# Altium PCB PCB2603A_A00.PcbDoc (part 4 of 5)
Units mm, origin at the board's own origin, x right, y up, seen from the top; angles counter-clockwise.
Board outline 35.56 x 55.88 mm, 8 copper layers (Top Layer, Signal Layer 1, Signal Layer 2, Signal Layer 3, Signal Layer 4, Signal Layer 5, Signal Layer 6, Bottom Layer), stack 1.497 mm thick; 167 components, 113 nets, 4957 pads, 645 vias.
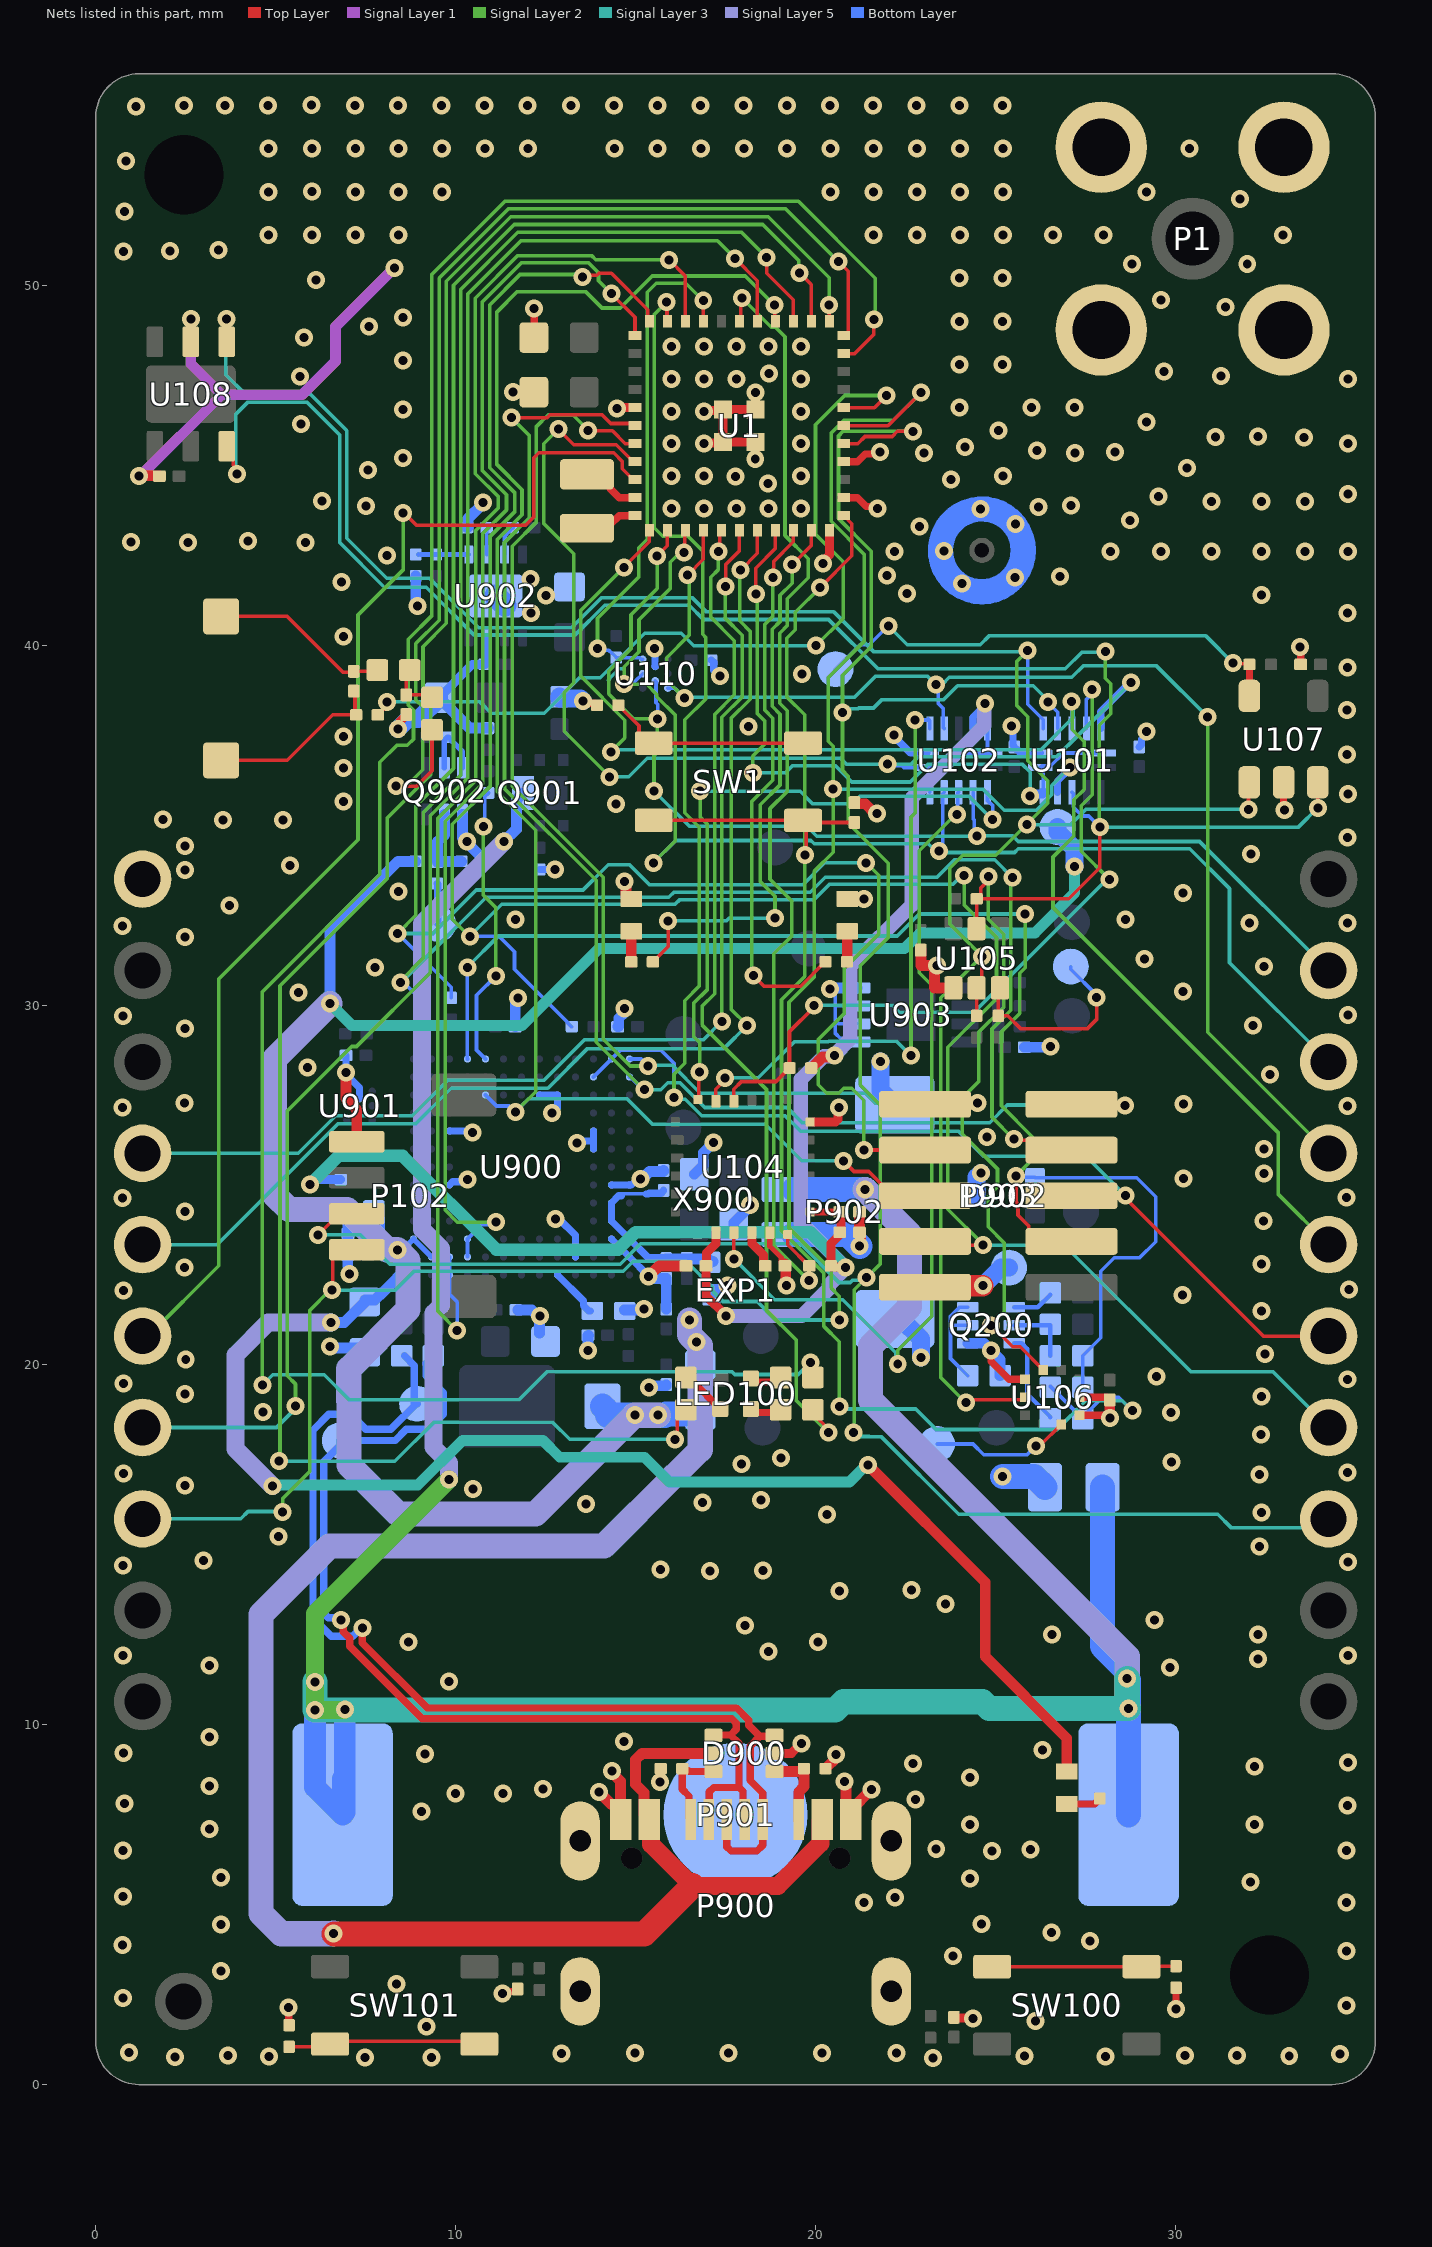
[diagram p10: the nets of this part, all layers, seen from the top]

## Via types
v1: diameter 0.5, hole 0.25, Top Layer to Bottom Layer, tented both sides, 645 vias

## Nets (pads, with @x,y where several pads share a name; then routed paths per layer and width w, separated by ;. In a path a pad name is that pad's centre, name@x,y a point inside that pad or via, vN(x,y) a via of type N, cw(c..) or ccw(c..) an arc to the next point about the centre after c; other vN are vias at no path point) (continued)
DBG_USB_DM: D900.4 P900.A7 P900.B7 R903.1 TPJ19.1 | length 28.1
  Top Layer w0.203: v1(6.82,12.916) 6.877,12.86 6.877,12.584 7.057,12.405 7.057,12.183 9.077,10.163 17.68,10.163 17.8,10.044 17.8,9.875 17.641,9.716 ; P900.B7@17.035,7.36 17.052,7.377 17.052,8.136 17.171,8.255 17.867,8.255 17.876,8.264 ; D900.4@17.165,9.7 17.233,9.7 17.249,9.716 17.641,9.716 ; P900.A7@18.035,7.36 17.987,7.408 17.987,8.153 17.876,8.264 ; 17.641,9.716 17.876,9.481 17.876,8.264
  Bottom Layer w0.203: v1(6.82,12.916) 6.764,12.973 6.464,12.973 6.339,13.098 6.339,17.311 6.78,17.752 TPJ19.1@6.78,17.9 8.32,17.9 8.631,18.211 9.252,18.211 9.659,18.618 9.659,19.222 9.18,19.7 9.18,19.933 9.182,19.934 9.182,20.052 R903.1@9.38,20.25
DBG_USB_DP: D900.3 P900.A6 P900.B6 R904.1 TPJ18.1 | length 30.2
  Top Layer w0.203: v1(7.407,12.694) 7.407,12.27 9.21,10.467 17.806,10.467 18.146,10.127 18.146,9.984 18.455,9.675 ; P900.A6@17.535,7.36 17.535,6.607 17.654,6.488 18.375,6.488 18.533,6.647 18.533,7.358 P900.B6@18.535,7.36 18.531,7.364 18.531,8.101 18.185,8.447 18.185,9.405 18.455,9.675 ; D900.3@18.865,9.7 18.84,9.675 18.455,9.675
  Bottom Layer w0.203: v1(7.407,12.694) 7.373,12.694 7.139,12.46 6.544,12.46 6.036,12.968 6.036,18.186 6.478,18.629 7.082,18.629 7.503,18.208 8.199,18.208 8.911,18.92 TPJ18.1@8.93,18.92 8.851,18.92 8.851,19.979 R904.1@8.58,20.25
DBG_VBUS: C901.1 D901.2 L901.2 R917.2 TPJ12.1 U900.A11 U900.B12 | length 62.2
  Signal Layer 5 w0.7: v1(6.511,30.044) 4.966,28.499 4.966,24.725 5.376,24.315 6.981,24.315 8.096,23.2 8.38,23.2 8.68,22.9 8.68,21.538 7.032,19.891 7.032,19.005 7.035,19.002 7.035,17.22 8.401,15.854 12.219,15.854 14.965,18.6 v1(15.63,18.6)
  Signal Layer 3 w0.305: v1(6.511,30.044) 7.12,29.434 11.849,29.434 13.984,31.569 22.473,31.569 22.913,32.008 26.1,32.008 27.201,33.109 v1(27.201,33.852)
  Bottom Layer w0.152: v1(8.382,23.198) 8.419,23.235 8.565,23.235 U900.A11@8.83,23.5 U900.B12@9.33,23
  Bottom Layer w0.2: C901.1@7.73,24.3 7.935,24.095 7.935,23.645 v1(8.382,23.198)
  Bottom Layer w0.305: v1(6.511,30.044) 6.511,32.102 8.404,33.995 R917.2@8.89,33.995
  Bottom Layer w0.5: TPJ12.1@26.73,34.95 26.73,34.815 27.201,34.343 v1(27.201,33.852)
  Bottom Layer w0.7: D901.2@14.08,18.85 D901.2@14.175,18.755 ; D901.2@14.23,18.6 v1(14.98,18.6) v1(15.63,18.6) 15.82,18.6 15.85,18.631 16.781,18.631 L901.2@16.8,18.65
DBG_VREGO: C902.1 LED900.1 U900.A12 | length 38.8
  Top Layer w0.3: v1(21.462,17.214) 24.716,13.96 24.716,11.892 26.985,9.623 LED900.1@26.985,8.7
  Signal Layer 5 w0.5: v1(4.908,16.633) 3.878,17.663 3.878,20.268 4.786,21.176 v1(6.53,21.176)
  Signal Layer 3 w0.3: v1(4.908,16.633) 4.936,16.66 8.949,16.66 10.189,17.9 12.425,17.9 12.894,17.431 15.252,17.431 15.94,16.743 20.943,16.743 21.414,17.214 v1(21.462,17.214)
  Bottom Layer w0.2: 8.43,22.475 8.43,22.6 U900.A12@8.83,23
  Bottom Layer w0.3: v1@6.531,21.175 6.905,21.175 C902.1@7.48,21.75 ; C902.1@7.48,21.8 7.755,21.8 7.98,22.025 7.987,22.025 8.28,22.318 8.28,22.325 8.43,22.475
DEBUG_PTI_DATA: P903.10 U1.29 U900.N1 | length 34.7
  Top Layer w0.1: v1(13.683,45.973) 13.696,45.96 14.358,45.96 14.718,45.6 U1.29@14.933,45.6
  Top Layer w0.102: P903.10@23.045,27.24 23.081,27.276 v1(24.505,27.276)
  Signal Layer 2 w0.1: v1(13.683,45.973) 13.252,46.404 12.572,46.404 12.246,46.078 12.246,43.422 11.571,42.747 11.571,39.442 11.572,39.441 11.572,36.08 14.105,33.547 14.105,29.052 14.852,28.305 v1(15.35,28.305)
  Signal Layer 3 w0.1: v1(15.35,28.305) 15.37,28.325 16.03,28.325 16.802,27.552 21.389,27.552 21.665,27.276 v1(24.505,27.276)
  Bottom Layer w0.1: U900.N1@14.83,28.5 15.155,28.5 v1(15.35,28.305)
DEBUG_PTI_FRAME: P903.9 U1.28 U900.N2 | length 40.5
  Top Layer w0.1: v1(11.548,46.326) 12.545,46.326 12.623,46.404 14.07,46.404 14.314,46.16 14.925,46.16 U1.28@14.985,46.1 ; P903.9@27.115,27.24 27.134,27.221 28.587,27.221 v1(28.596,27.212)
  Signal Layer 2 w0.1: v1(11.548,46.326) 12.046,45.828 12.046,43.541 11.36,42.855 11.36,36.01 13.905,33.465 13.905,28.969 15.226,27.648 v1(15.255,27.648)
  Signal Layer 3 w0.1: v1(15.255,27.648) 15.705,27.648 15.894,27.837 16.235,27.837 16.92,27.152 19.212,27.152 19.631,26.732 24.842,26.732 25.332,27.222 28.586,27.222 v1(28.596,27.212)
  Bottom Layer w0.1: U900.N2@14.83,28 14.857,28 15.209,27.648 v1(15.255,27.648)
DEBUG_RESET: D902.1 P903.3 R206.1 R209.1 U900.D1 | length 40.4
  Top Layer w0.1: v1(25.573,25.25) 25.573,24.528 25.63,24.471 25.63,24.158 25.93,23.859 25.93,23.748 26.248,23.43 P903.3@27.115,23.43
  Signal Layer 2 w0.1: v1(25.573,25.25) 26.028,25.705 26.028,26.343 25.171,27.2 25.171,29.257 25.681,29.767 25.681,30.886 25.83,31.035 v1(25.83,32.531)
  Signal Layer 3 w0.1: v1(10.326,31.042) 10.326,31.052 11.193,31.919 22.271,31.919 22.883,32.531 v1(25.83,32.531)
  Bottom Layer w0.1: v1(10.326,31.042) 10.328,31.04 10.328,28.502 U900.D1@10.33,28.5 ; v1(25.573,25.25) 25.613,25.21 26.095,25.21 D902.1@26.105,25.2 28.931,25.2 29.455,24.676 29.455,23.425 29.005,22.975 28.305,22.975 27.93,22.6 27.93,20.75 R206.1@27.43,20.25 R209.1@27.43,19.4
DEBUG_SWCLK: P903.8 R920.2 U1.13 | length 59.6
  Top Layer w0.1: v1(19.557,50.35) 19.885,50.022 U1.13@19.885,49 ; v1(21.345,25.97) P903.8@23.045,25.97
  Signal Layer 2 w0.1: v1(8.388,31.989) 8.895,32.495 8.895,35.53 9.941,36.576 9.941,50.004 11.628,51.691 18.532,51.691 19.532,50.691 19.532,50.375 v1(19.557,50.35) ; v1(21.345,25.97) 21.345,27.351 21.005,27.691 20.784,27.691 20.645,27.552 20.314,27.552 20.079,27.786 20.079,29.043 20.805,29.769 20.805,31.025 21.756,31.976 21.756,33.608 v1(21.411,33.952)
  Signal Layer 3 w0.1: v1(8.388,31.989) 9.362,31.989 10.57,33.197 13.541,33.197 14.242,33.898 14.834,33.898 15.394,33.338 19.643,33.338 20.257,33.952 v1(21.411,33.952)
  Bottom Layer w0.1: v1(8.388,31.989) 9.88,30.497 R920.2@9.88,30.2
DEBUG_SWDIO: P903.7 R919.2 U1.14 | length 60.3
  Top Layer w0.1: v1(18.645,50.773) 18.645,50.34 19.385,49.6 U1.14@19.385,49 ; v1(25.515,26.271) 25.542,26.244 26.841,26.244 P903.7@27.115,25.97
  Signal Layer 2 w0.1: v1(8.462,30.629) 8.462,30.663 9.095,31.296 9.095,35.346 10.141,36.392 10.141,49.885 11.73,51.474 17.944,51.474 v1(18.645,50.773) ; v1(25.473,33.545) 25.43,33.502 25.43,29.858 24.905,29.333 24.905,26.881 v1(25.515,26.271)
  Signal Layer 3 w0.1: v1(8.462,30.629) 8.484,30.629 10.852,32.997 15.927,32.997 16.068,33.138 19.855,33.138 20.27,33.552 23.379,33.552 23.864,34.038 24.98,34.038 v1(25.473,33.545)
  Bottom Layer w0.1: v1(8.462,30.629) 8.561,30.629 8.98,30.21 R919.2@8.98,30.2
DEBUG_SWO: P903.6 U1.15 U900.E3 | length 46.5
  Top Layer w0.1: v1(18.863,49.451) 18.874,49.44 18.874,49.011 U1.15@18.885,49 ; v1(20.775,25.671) 21.071,25.375 21.479,25.375 P903.6@21.82,25.034 ; P903.6@21.82,25.033 22.153,24.7 P903.6@23.045,24.7
  Signal Layer 2 w0.1: v1(11.658,27.025) 12.226,27.593 12.226,34.861 11.16,35.927 11.16,42.937 11.846,43.624 11.846,44.322 11.148,45.02 11.148,49.262 11.714,49.828 13.611,49.828 14.068,49.37 14.574,49.37 15.465,50.261 18.053,50.261 v1(18.863,49.451)
  Signal Layer 3 w0.1: v1(11.658,27.025) 11.658,27.028 12.03,27.4 14.756,27.4 15.472,26.685 18.606,26.685 19.62,25.671 v1(20.775,25.671)
  Bottom Layer w0.1: U900.E3@10.83,27.5 11.135,27.195 11.485,27.195 11.655,27.025 v1(11.658,27.025)
EXP_HEADER4: EXP1.4 U1.35 U102.2 U110.D2 | length 32.1
  Top Layer w0.1: v1(15.6,42.48) 15.885,42.765 U1.35@15.885,43.2
  Signal Layer 2 w0.1: v1(15.514,35.945) 15.514,36.936 15.606,37.028 v1@15.606,37.945 ; v1(15.6,42.48) 15.6,41.578 14.873,40.85 14.873,39.899 14.253,39.279 14.253,38.646 14.945,37.955 v1(15.606,37.955)
  Signal Layer 3 w0.1: v1(15.514,35.945) 15.522,35.945 16.493,34.973 19.752,34.973 20.033,34.692 v1(24.492,34.692) 24.503,34.703 25.482,34.703 25.639,34.546 30.675,34.546 EXP1.4@34.261,30.96
  Bottom Layer w0.1: U110.D2@15.547,39.008 15.567,38.987 15.567,38.406 15.618,38.355 15.618,37.967 v1(15.606,37.955) ; U102.2@24.38,35.915 24.38,35.178 24.416,35.142 24.416,34.767 v1(24.492,34.692)
EXP_HEADER6: EXP1.6 U1.36 U102.4 U110.C3 | length 36.1
  Top Layer w0.1: v1(16.34,42.577) 16.363,42.599 16.363,43.178 U1.36@16.385,43.2
  Signal Layer 2 w0.1: v1(14.686,38.917) 14.686,39.403 15.097,39.815 15.097,40.705 15.968,41.577 15.968,42.303 16.242,42.577 v1(16.34,42.577) ; v1@14.692,38.911 15.314,38.911 15.592,38.633 15.592,38.57 16.102,38.06 16.102,34.56 v1(15.495,33.953)
  Signal Layer 3 w0.1: v1(15.495,33.953) 16.114,34.572 19.87,34.572 19.963,34.479 23.132,34.479 23.33,34.281 v1(23.438,34.281) 23.481,34.238 25.531,34.238 25.639,34.346 30.399,34.346 31.508,33.237 31.508,31.173 EXP1.6@34.261,28.42
  Bottom Layer w0.1: v1(14.686,38.917) 14.762,38.994 14.982,38.994 U110.C3@15.197,39.208 ; v1@23.536,34.488 23.536,35.871 U102.4@23.58,35.915
EXP_HEADER7: EXP1.7 U1.39 | length 31.9
  Top Layer w0.1: v1(17.494,41.626) 17.511,41.643 17.511,42.243 17.885,42.617 U1.39@17.885,43.2
  Signal Layer 2 w0.1: v1(17.398,29.546) 17.398,37.994 17.963,38.558 17.963,40.279 17.488,40.755 17.488,41.62 v1(17.494,41.626)
  Signal Layer 3 w0.1: EXP1.7@1.3,25.88 5.625,25.88 6.666,26.921 8.796,26.921 9.787,27.912 12.456,27.912 13.582,29.037 16.889,29.037 v1(17.398,29.546)
EXP_HEADER8: EXP1.8 U1.37 U102.9 U110.E1 | length 36.4
  Top Layer w0.1: v1(16.447,41.948) 16.885,42.386 U1.37@16.885,43.2
  Signal Layer 2 w0.1: v1(16.361,38.53) 16.359,38.53 15.867,39.022 15.867,39.654 16.488,40.275 16.488,41.907 v1(16.447,41.948) ; v1(30.898,38.002) 30.898,29.243 EXP1.8@34.261,25.88
  Signal Layer 3 w0.1: v1(16.361,38.53) 16.389,38.558 21.089,38.558 21.672,39.141 23.111,39.141 23.35,38.902 v1(23.354,38.902) ; v1@23.354,38.907 23.516,38.907 23.714,39.106 27.125,39.106 27.443,39.424 29.477,39.424 v1(30.898,38.002)
  Bottom Layer w0.1: U110.E1@15.897,38.808 16.084,38.808 v1(16.361,38.53) ; v1(23.354,38.902) 23.416,38.84 23.416,38.38 23.552,38.243 23.552,37.713 U102.9@23.58,37.685
EXP_HEADER9: EXP1.9 U1.40 | length 33.8
  Top Layer w0.1: v1(17.92,42.087) 18.385,42.552 U1.40@18.385,43.2
  Signal Layer 2 w0.1: v1(17.92,42.087) 17.894,42.061 17.894,40.675 18.186,40.383 18.186,38.499 17.654,37.967 17.654,29.886 v1(18.103,29.437)
  Signal Layer 3 w0.1: EXP1.9@1.3,23.34 3.368,23.34 6.731,26.702 8.891,26.702 9.88,27.691 12.565,27.691 13.664,28.79 17.456,28.79 v1(18.103,29.437)
EXP_HEADER10: EXP1.10 U1.34 U101.10 | length 40.9
  Top Layer w0.1: v1(14.674,42.163) 15.385,42.874 U1.34@15.385,43.2
  Signal Layer 2 w0.1: v1(14.312,37.035) 14.699,37.422 14.699,37.918 13.482,39.134 13.482,40.971 v1@14.673,42.161 ; v1(27.114,38.433) 27.137,38.409 27.137,37.652 27.47,37.319 27.47,35.992 27.18,35.702 27.18,34.694 26.601,34.115 26.601,32.71 32.866,26.446 32.866,24.735 EXP1.10@34.261,23.34
  Signal Layer 3 w0.1: v1(14.312,37.035) 14.373,37.096 26.268,37.096 27.168,37.997 27.168,38.378 v1(27.114,38.433)
  Bottom Layer w0.1: v1(27.114,38.433) 27.122,38.424 27.122,37.693 U101.10@27.13,37.685
EXP_HEADER11: EXP1.11 U1.31 | length 34.8
  Top Layer w0.1: v1(8.541,43.67) 8.578,43.67 8.914,43.334 11.943,43.334 12.17,43.561 12.17,45.202 12.314,45.345 14.391,45.345 14.63,45.106 14.63,44.905 14.935,44.6 U1.31@14.985,44.6
  Signal Layer 2 w0.1: EXP1.11@1.3,20.8 1.466,20.8 3.417,22.751 3.417,30.725 7.287,34.595 7.287,40.84 8.55,42.103 8.55,43.661 v1(8.541,43.67)
EXP_HEADER12: EXP1.12 P903.5 U1.21 U900.L2 U900.M1 | length 50.6
  Top Layer w0.1: v1(15.866,49.533) 15.875,49.523 15.875,49.01 U1.21@15.885,49 ; P903.5@27.115,24.7 27.117,24.702 v1(28.616,24.702) ; v1@28.579,24.665 32.444,20.8 EXP1.12@34.261,20.8
  Signal Layer 2 w0.1: v1(15.866,49.533) 15.523,49.19 15.523,43.262 15.76,43.025 16.458,43.025 16.865,42.618 16.865,40.3 16.947,40.218 16.947,38.502 16.369,37.924 16.369,35.342 16.774,34.937 16.774,30.528 16.369,30.122 16.369,28.38 16.069,28.08 v1(16.069,27.437)
  Signal Layer 3 w0.1: v1(16.069,27.437) 16.122,27.384 16.382,27.384 16.842,26.924 19.156,26.924 19.587,26.493 23.976,26.493 24.669,25.801 27.517,25.801 v1(28.616,24.702)
  Bottom Layer w0.1: U900.L2@13.83,28 U900.M1@14.33,28.5 14.58,28.75 15.701,28.75 16.069,28.382 v1(16.069,27.437)
EXP_HEADER13: EXP1.13 U1.16 | length 47.9
  Top Layer w0.1: v1(17.764,50.75) 18.385,50.129 U1.16@18.385,49
  Signal Layer 2 w0.1: v1(5.551,18.858) 5.551,19.466 5.32,19.698 5.32,27.055 7.113,28.849 7.248,28.849 9.296,30.897 9.296,35.264 10.341,36.309 10.341,49.762 11.818,51.238 17.276,51.238 v1(17.764,50.75)
  Signal Layer 3 w0.1: EXP1.13@1.3,18.26 5.023,18.26 5.551,18.788 v1(5.551,18.858)
EXP_HEADER14: EXP1.14 P903.4 R921.2 U1.22 | length 67.9
  Top Layer w0.1: v1(13.527,50.228) 13.584,50.284 13.927,50.284 13.977,50.334 14.33,50.334 15.339,49.325 15.339,49.046 U1.22@15.385,49
  Top Layer w0.102: P903.4@23.045,23.43 23.15,23.325 v1(24.655,23.325)
  Signal Layer 2 w0.1: v1(24.133,33.598) 24.133,32.779 25.03,31.882 25.03,30.174 23.68,28.824 23.68,24.325 24.655,23.35 v1(24.655,23.325)
  Signal Layer 2 w0.102: v1(10.394,31.911) 10.379,31.911 9.909,32.381 9.909,35.022 10.959,36.071 10.959,43.021 11.639,43.701 11.639,44.242 10.947,44.934 10.947,49.457 11.79,50.301 13.454,50.301 v1(13.527,50.228)
  Signal Layer 3 w0.1: v1(10.394,31.911) 11.28,32.797 16.097,32.797 16.22,32.921 19.955,32.921 20.387,33.352 23.813,33.352 24.059,33.598 v1(24.133,33.598) ; v1(24.655,23.325) 26.917,23.325 30.437,19.805 32.716,19.805 EXP1.14@34.261,18.26
  Bottom Layer w0.1: 11.206,31.911 11.637,31.479 11.637,30.993 13.11,29.52 13.11,29.51 13.22,29.4 R921.2@13.23,29.4
  Bottom Layer w0.102: v1(10.394,31.911) 11.206,31.911
EXP_HEADER15: EXP1.15 P102.4 U1.6 U101.4 | length 68.5
  Top Layer w0.1: v1(6.569,22.076) 6.587,22.094 6.587,22.952 6.835,23.2 P102.4@7.255,23.2 ; U1.6@20.785,46.1 22.014,46.1 v1(22.931,47.017)
  Signal Layer 2 w0.1: EXP1.15@1.3,15.72 EXP1.15@1.442,15.578 ; v1(5.192,15.906) 5.192,16.288 5.951,17.047 5.951,21.522 6.505,22.076 v1(6.569,22.076) ; v1(20.665,21.248) 20.665,21.909 20.436,22.138 20.436,22.634 19.266,23.804 19.266,30.074 19.969,30.777 19.969,33.722 20.491,34.245 v1(20.491,35.997) 20.491,37.194 20.352,37.332 20.352,39.104 21.352,40.103 21.352,42.53 20.441,43.441 20.441,45.899 20.791,46.248 22.162,46.248 v1(22.931,47.017)
  Signal Layer 3 w0.1: EXP1.15@1.3,15.72 4.027,15.72 4.233,15.926 5.172,15.926 v1(5.192,15.906) ; v1(6.569,22.076) 8.318,22.076 8.841,22.6 14.658,22.6 14.935,22.877 16.408,22.877 17.151,22.134 17.151,22.041 17.429,21.762 18.379,21.762 18.893,21.248 v1(20.665,21.248) ; v1(20.491,35.997) 24.657,35.997 25.243,35.41 26.133,35.41 26.563,35.84 26.563,36.099 v1(27.07,36.605)
  Bottom Layer w0.1: U101.4@26.73,35.915 26.78,35.965 U101.4@26.78,36.205 ; v1@27.07,36.595 v1(27.07,36.605)
  Bottom Layer w0.2: U101.4@26.73,35.915 26.73,36.226 27.07,36.566 v1@27.07,36.595
EXP_HEADER16: EXP1.16 P102.3 U1.5 U101.9 | length 73.1
  Top Layer w0.1: v1(6.175,23.615) 6.185,23.615 6.755,24.185 6.755,24.2 P102.3@7.255,24.2 ; U1.5@20.785,45.6 21.176,45.6 21.376,45.8 22.13,45.8 22.273,45.943 v1(22.714,45.943)
  Signal Layer 2 w0.1: v1(21.058,18.114) 21.08,18.136 21.08,22.085 v1(21.42,22.425) 21.795,22.8 21.795,27.225 21.241,27.78 21.241,31.091 22.027,31.877 22.027,33.941 20.912,35.056 20.912,36.362 20.752,36.521 20.752,38.255 20.752,39.163 21.553,39.964 21.553,42.611 20.641,43.523 20.641,45.816 20.768,45.943 v1(22.714,45.943)
  Signal Layer 3 w0.1: v1(6.175,23.615) 7.349,23.615 8.166,22.798 8.756,22.798 8.759,22.8 14.575,22.8 15.14,23.365 19.58,23.365 20.655,22.29 20.97,22.29 21.029,22.348 21.343,22.348 v1(21.42,22.425) ; v1(20.752,38.13) 20.86,38.238 21.185,38.238 21.202,38.255 21.616,38.255 21.85,38.489 23.566,38.489 23.95,38.873 26.057,38.873 26.46,38.47 v1(26.46,38.421) ; v1(21.058,18.114) 21.161,18.01 21.495,18.01 21.508,17.998 21.837,17.998 23.984,15.85 31.177,15.85 31.549,15.478 34.019,15.478 EXP1.16@34.261,15.72
  Bottom Layer w0.1: v1(26.46,38.421) 26.46,38.41 26.73,38.139 U101.9@26.73,37.685
FLASH_SPI_CS: R100.1 U1.19 U110.A3 | length 14.3
  Top Layer w0.1: v1(16.882,49.575) 16.883,49.574 16.883,49.002 U1.19@16.885,49
  Signal Layer 2 w0.1: v1(13.944,39.904) 13.944,40.751 15.086,41.893 15.086,42.706 15.323,42.943 15.323,49.811 15.573,50.061 16.396,50.061 v1(16.882,49.575)
  Bottom Layer w0.1: v1(13.944,39.904) 13.993,39.855 14.26,39.855 14.34,39.775 14.35,39.775 14.46,39.665 R100.1@14.46,39.655 15.12,39.655 15.167,39.608 U110.A3@15.197,39.608
GND: C22.2 C23.2 C100.2 C101.2 C104.2 C105.2 C106.2 C107.2 C110.2 C111.2 C112.2 C113.2 C114.2 C115.2 C142.2 C145.2 C199.2 C900.2 C901.2 C902.2 C903.2 C904.2 C905.2 C907.2 C908.2 C909.2 C910.2 C911.2 C914.2 C915.2 C916.2 C917.2 C918.2 C919.2 C920.2 C921.2 C923.2 C924.2 C925.2 C926.2 D900.2 D902.3 EXP1.1 LED0.2 LED1.2 P1.2 P1.3 P1.4 P1.5 P102.1 P900.A1_B12 P900.B1_A12 P900.S1 P900.S2 P900.S3 P900.S4 P901.2 P902.1 P902.3 P902.4 P903.2 Q200.1 Q902.1 R6.1 R141.2 R144.2 R208.1 R620.1 R621.1 R909.1 R915.1 R916.1 R933.2 TP1.2 TPJ13.1 U1.2 U1.4 U1.27 U1.44 U1.45 U1.46 U1.47 U1.48 U101.7 U102.7 U104.11 U104.18 U105.1 U106.3 U106.8 U106.9 U107.2 U108.2 U110.B2 U900.C5 U900.C8 U900.H3 U900.J3 U900.K11 U900.K12 U900.L5 U900.L6 U900.M8 U900.M11 U900.N8 U900.N12 U901.B2 U902.3 U902.9 U903.1 U903.2 U903.3 U903.4 X900.2 X900.4 | length 99.1
  Top Layer w0.15: U104.11@18.73,23.675 18.73,23.301 19.05,22.981 19.05,22.835 19.085,22.8 C106.2@19.155,22.8
  Top Layer w0.2: v1(5.357,2.142) 5.365,2.135 5.365,1.656 R144.2@5.372,1.648 ; v1(11.307,2.528) 11.364,2.585 11.66,2.585 11.72,2.645 C145.2@11.72,2.655 ; v1(11.595,47.038) 12.167,47.038 C111.2@12.173,47.032 ; v1(12.184,49.363) 12.184,48.372 C110.2@12.195,48.361 ; v1(13.54,38.45) 13.622,38.45 13.684,38.388 13.867,38.388 R6.1@13.927,38.328 ; U1.2@20.71,44.1 21.17,44.1 21.413,43.857 21.671,43.857 v1(21.729,43.799) ; U1.4@20.79,45.106 20.854,45.106 20.86,45.1 21.17,45.1 21.385,45.316 21.739,45.316 v1(21.796,45.373) ; v1(24.88,20.4) 24.88,20.1 25.38,19.6 U106.3@25.823,19.6 ; U106.8@27.337,18.6 28.105,18.6 v1(28.18,18.525) ; U106.9@27.337,19.1 28.105,19.1 C112.2@28.18,19.025 ; v1(30.022,2.105) R141.2@30.022,2.69 ; U107.2@33.01,36.19 33.01,35.455 v1(33.039,35.427) ; v1(33.461,39.955) 33.485,39.931 C113.2@33.485,39.465
  Top Layer w0.25: v1(8.405,37.677) 8.452,37.725 8.452,37.877 8.625,38.05 C199.2@8.625,38.07 ; v1(14.484,46.583) 14.501,46.6 U1.27@14.985,46.6 ; v1(15.679,8.403) 15.69,8.414 15.69,8.77 R621.1@15.7,8.781 ; v1(16.9,45.6) 16.925,45.625 17.41,45.625 U1.48@17.435,45.65 ; v1(16.9,46.5) 16.925,46.525 17.41,46.525 U1.47@17.435,46.55 ; v1(18.327,45.177) 18.331,45.181 18.331,45.646 U1.45@18.335,45.65 U1.48@17.435,45.65 ; v1(18.339,47.026) 18.337,47.024 18.337,46.552 U1.46@18.335,46.55 U1.47@17.435,46.55 ; D900.2@18.865,9.2 19.329,9.2 19.6,9.471 v1(19.611,9.471) ; U104.18@19.955,26.75 20.555,26.75 20.63,26.825 20.63,27.125 v1(20.655,27.15) ; v1(20.209,42.27) 20.209,42.325 20.385,42.501 U1.44@20.385,43.2 ; C142.2@23.85,1.869 23.864,1.855 24.361,1.855 v1(24.375,1.84) ; U1.48@17.435,45.65 U1.47@17.435,46.55
  Top Layer w0.3: v1@1.355,44.726 1.301,44.726 1.316,44.71 1.755,44.71 C114.2@1.765,44.7 ; U108.2@2.64,48.43 v1(2.64,49.065) ; v1(6.955,28.125) 6.955,27.4 7.255,27.1 P102.1@7.255,26.2 ; v1@13.999,8.115 14.334,7.78 14.435,7.78 P900.A1_B12@14.585,7.63 ; v1(14.348,8.717) 14.348,8.663 14.585,8.426 P900.A1_B12@14.585,7.36 ; v1(14.699,33.434) 14.737,33.395 14.737,33.025 14.812,32.95 LED1.2@14.885,32.95 ; v1(15.356,22.451) 15.655,22.75 C115.2@16.405,22.75 ; C106.2@19.155,22.8 C106.2@19.155,22.75 19.163,22.75 19.173,22.74 19.173,22.226 v1(19.191,22.208) ; R620.1@20.279,8.789 20.289,8.789 20.575,9.075 v1(20.575,9.167) ; v1(20.811,8.424) 20.849,8.386 20.849,7.661 P900.B1_A12@20.88,7.63 ; P900.B1_A12@20.985,7.36 20.985,7.63 21.55,8.195 v1(21.554,8.195) ; C100.2@21.083,35.623 21.083,35.603 21.093,35.593 21.382,35.593 21.652,35.324 v1(21.706,35.324) ; C104.2@21.225,23.682 C105.2@21.225,24.25 ; v1(21.229,23.298) 21.259,23.327 C104.2@21.259,23.672 ; v1(21.355,32.952) v1(21.355,32.952) LED0.2@20.886,32.951 ; C107.2@22.93,31.525 22.93,31.1 v1(23.38,31.1) 23.305,31.025 23.305,30.475 U105.1@23.83,30.475 ; v1(26.535,28.842) v1@26.535,28.857 ; v1(28.18,18.525) C112.2@28.18,19.025 ; LED0.2@20.886,32.951 LED0.2@20.885,32.95 LED0.2@20.886,32.951
  Top Layer w0.6: P903.2@23.045,22.16 23.085,22.2 v1(24.655,22.2)
  Signal Layer 1 w0.2: v1(30.022,2.105) v1@30.022,2.142
  Signal Layer 1 w0.3: v1(1.2,44.7) 1.235,44.7 3.498,46.963 ; v1(2.64,49.065) 2.64,47.821 3.498,46.963 ; v1(8.296,50.486) 6.661,48.85 6.661,47.889 5.734,46.963 3.498,46.963
  Signal Layer 3 w0.1: 14.25,39.028 14.286,39.064 14.286,39.083 14.548,39.345 14.637,39.345
  Bottom Layer w0.1: v1(20.405,30.45) 20.555,30.3 20.555,30 ; U903.1@21.155,28.975 21.055,29.075 20.689,29.075 20.555,29.209 20.555,29.575 ; U903.2@21.155,29.475 20.655,29.475 20.555,29.575 ; U903.3@21.155,29.975 20.58,29.975 20.555,30 ; 20.555,29.575 20.555,30
  Bottom Layer w0.2: U900.C8@9.83,25 9.918,25.088 10.268,25.088 v1(10.326,25.146) ; U900.C5@9.83,26.5 10.438,26.5 v1(10.475,26.463) ; U900.H3@12.33,27.5 U900.J3@12.83,27.5 12.83,27.125 v1@12.705,27 ; R915.1@12.34,33.77 12.759,33.77 v1(12.76,33.771) ; v1@12.73,24.05 v1(12.78,24.05) 12.88,24.05 13.33,23.6 U900.K11@13.33,23.5 U900.K12@13.33,23 ; v1@13.375,26.22 13.8,26.22 13.83,26.25 ; U900.L6@13.83,26 13.83,26.25 ; U900.L5@13.83,26.5 13.83,26.25 ; U900.M11@14.33,23.5 U900.N12@14.83,23 15.354,22.476 v1(15.356,22.451) ; U900.M8@14.33,25 14.886,25 15.056,25.17 v1(15.137,25.17) ; v1(15.534,39.914) 15.545,39.903 15.545,39.41 U110.B2@15.547,39.408 ; C101.2@17.094,39.588 17.114,39.588 17.174,39.528 17.174,39.3 17.332,39.142 v1(17.347,39.142) ; v1(22.189,37.499) 22.189,37.459 22.648,37 U102.7@23.095,37 ; v1(25.447,37.753) 25.489,37.712 25.489,37.216 C23.2@25.53,37.175 25.53,37.155 25.59,37.095 25.612,37.095 25.707,37 U101.7@26.245,37 ; C22.2@29,37.175 29.06,37.235 29.06,37.384 29.195,37.519 v1(29.195,37.6)
  Bottom Layer w0.203: C914.2@6.955,28.6 v1(6.955,28.125) 6.955,28.075 7.33,27.7 U901.B2@7.33,27.4
  Bottom Layer w0.25: C915.2@9.54,38.545 10.465,39.47 C916.2@10.815,39.47 10.865,39.52 U902.3@10.865,40.22 ; v1@19.611,9.46 v1(19.611,9.471)
  Bottom Layer w0.3: C901.2@6.83,24.325 7.005,24.15 C910.2@7.005,23.65 C926.2@7.005,23.05 v1@7.005,22.75 ; R909.1@8.89,41.92 8.89,41.26 8.903,41.248 8.903,41.127 v1(8.941,41.089) ; C908.2@11.655,29.4 11.655,30.11 11.733,30.188 v1(11.733,30.194) ; C911.2@11.729,21.525 12.115,21.525 12.287,21.353 v1(12.341,21.353) 12.341,21.271 12.33,21.261 C907.2@12.33,20.88 ; v1(13.68,20.406) 13.678,20.408 13.678,20.815 C923.2@13.701,20.815 ; C925.2@14.505,29.4 14.525,29.4 14.535,29.41 14.535,29.631 14.659,29.755 14.659,29.87 v1(14.697,29.908) ; C900.2@14.684,21.534 14.691,21.527 15.206,21.527 v1(15.234,21.555) ; v1(15.137,25.17) 15.191,25.17 15.391,25.37 15.77,25.37 15.78,25.38 C905.2@15.78,25.4 ; v1(15.356,22.451) 15.407,22.4 C904.2@15.855,22.4 C924.2@15.855,21.55 ; v1(15.371,19.37) 15.425,19.37 15.475,19.42 15.845,19.42 15.855,19.43 C909.2@15.855,19.45 ; X900.2@16.63,25.3 16.88,25.55 16.88,25.894 17.139,26.154 17.139,26.158 v1(17.16,26.179) ; C903.2@17.105,21.95 17.205,22.05 17.205,22.1 17.39,22.1 17.496,22.206 v1(17.551,22.206) ; X900.4@17.73,23.9 17.73,23.95 18.186,24.406 v1(18.186,24.436) ; v1(20.405,30.45) 20.43,30.475 U903.4@21.155,30.475 ; Q200.1@24.23,20.6 24.68,20.6 v1(24.88,20.4) 25.13,20.15 R208.1@25.13,19.7 ; C919.2@25.805,28.825 26.514,28.825 26.531,28.842 v1(26.535,28.842)
  Bottom Layer w0.305: v1(6.514,20.505) 6.552,20.467 7.363,20.467 C902.2@7.48,20.35 ; C915.2@9.54,38.545 10.39,37.695 R933.2@10.915,37.695 ; v1@10.19,34.636 10.747,34.078 10.747,34.003 10.755,33.995 R916.1@10.765,33.995 ; Q902.1@10.19,35.295 10.192,35.293 10.192,34.715 10.31,34.598 v1(10.31,34.545) ; C918.2@10.315,43.27 10.335,43.27 10.343,43.278 10.343,43.517 10.758,43.932 v1(10.758,43.96)
  Bottom Layer w0.5: v1(8.405,37.677) 8.683,37.955 8.975,37.955 9.54,38.52 C915.2@9.54,38.545 ; C920.2@12.89,38.57 12.89,38.52 13.47,38.52 v1(13.54,38.45) ; v1(21.805,28.425) 21.805,27.625 P902.3@22.205,27.225 ; P902.4@22.205,21.275 22.382,21.275 22.932,20.725 v1(22.932,20.202) ; D902.3@24.455,24.7 24.48,24.725 24.48,25.216 v1(24.602,25.337) ; v1(24.655,22.2) 25.155,22.7 TPJ13.1@25.38,22.7
  Bottom Layer w0.635: U902.9@11.115,41.37 U902.9@11.374,41.111
  Bottom Layer w0.7: P902.1@19.405,23.625 20.902,23.625 v1(21.229,23.298) ; v1(25.205,16.9) 26.08,16.9 C921.2@26.38,16.6
  other v1: 23.273,0.738 2.207,0.764 7.485,0.75 9.332,0.75 4.817,0.776 25.815,0.791 28.065,0.778 33.167,0.794 3.678,0.801 30.269,0.812 31.717,0.801 34.579,0.846 12.943,0.864 0.918,0.886 14.98,0.875 17.58,0.875 20.18,0.875 22.257,0.875 9.194,1.614 26.11,1.763 34.753,2.193 0.758,2.403 8.351,2.794 3.48,3.152 23.817,3.575 34.753,3.708 0.749,3.878 27.626,3.99 26.566,4.231 3.48,4.452 24.609,4.466 21.355,5.059 34.753,5.056 22.205,5.2 0.758,5.231 32.097,5.632 24.294,5.732 3.48,5.752 0.763,6.502 24.904,6.495 34.753,6.5 25.972,6.533 23.357,6.55 3.155,7.1 24.294,7.222 32.197,7.232 9.046,7.593 34.792,7.75 0.793,7.813 22.777,7.924 11.315,8.082 9.993,8.093 13.983,8.131 12.435,8.217 3.155,8.3 24.294,8.532 32.197,8.832 22.705,8.925 34.798,8.95 9.151,9.18 0.767,9.21 26.309,9.295 14.684,9.535 3.155,9.652 9.809,11.207 29.856,11.586 3.155,11.652 32.297,11.832 0.758,11.924 34.798,11.928 18.697,12.032 8.697,12.296 20.076,12.293 26.58,12.501 32.3,12.5 18.036,12.757 29.428,12.907 23.608,13.352 20.673,13.713 22.665,13.738 17.076,14.268 18.547,14.285 15.697,14.31 0.759,14.419 34.805,14.526 2.988,14.562 32.335,14.953 5.078,15.229 20.322,15.841 32.4,15.9 13.619,16.136 16.855,16.171 18.487,16.243 10.484,16.554 2.485,16.645 0.767,16.975 32.347,16.951 34.779,17.002 17.948,17.243 29.892,17.3 19.04,17.413 32.378,18.067 29.875,18.676 4.648,18.696 32.397,19.127 2.485,19.185 0.767,19.487 34.786,19.6 29.477,19.67 2.5,20.144 32.5,20.3 32.4,21.5 30.195,21.935 0.766,22.071 34.824,22.101 7.055,22.525 2.472,22.702 32.4,22.8 32.454,24.004 2.485,24.265 0.74,24.634 34.76,24.654 30.222,25.182 32.466,25.325 32.466,25.995 13.375,26.17 24.765,26.33 12.68,27 0.749,27.155 34.792,27.188 30.222,27.255 2.462,27.28 32.638,28.069 5.888,28.266 2.485,29.345 32.157,29.426 0.758,29.702 34.798,29.728 5.628,30.354 30.213,30.373 7.756,31.04 32.466,31.075 29.146,31.283 2.485,31.885 0.74,32.196 32.061,32.286 34.779,32.281 11.664,32.38 28.62,32.377 3.719,32.766 30.213,33.114 8.416,33.155 2.485,33.755 5.396,33.876 32.1,34.2 2.485,34.425 34.792,34.66 1.874,35.157 3.534,35.139 5.203,35.148 14.463,35.586 6.88,35.657 34.805,35.859 6.88,36.581 34.773,36.968 6.88,37.468 18.143,37.746 34.773,38.193 19.63,39.195 34.786,39.379 6.887,40.246 12.094,40.889 34.786,40.901 12.513,41.376 32.4,41.4 22.55,41.431 24.071,41.72 6.833,41.762 12.079,41.835 25.549,41.885 26.8,41.906 21.988,41.93 8.099,42.492 22.2,42.6 28.2,42.6 29.6,42.6 31,42.6 32.4,42.6 33.6,42.6 34.8,42.6 23.577,42.613 2.564,42.857 5.83,42.857 0.98,42.868 4.224,42.889 22.894,43.303 25.556,43.371 28.743,43.472 24.584,43.779 16,43.8 16.9,43.8 17.8,43.8 18.7,43.8 19.596,43.8 26.192,43.842 7.511,43.874 27.099,43.889 31,44 32.4,44 33.6,44 6.286,44.004 29.538,44.13 34.8,44.2 18.681,44.487 23.766,44.603 17.776,44.683 16,44.7 16.9,44.7 19.596,44.7 25.218,44.703 7.564,44.868 30.332,44.925 8.54,45.204 23.022,45.341 27.215,45.346 28.325,45.373 26.16,45.415 24.155,45.508 16,45.6 19.596,45.6 34.8,45.6 33.571,45.774 31.122,45.79 32.299,45.796 25.092,45.966 5.708,46.147 29.2,46.2 16,46.5 19.596,46.5 8.54,46.555 24,46.6 26,46.6 27.2,46.6 16,47.4 16.9,47.4 17.8,47.4 19.596,47.4 34.8,47.4 5.671,47.461 31.268,47.475 18.707,47.548 29.685,47.608 24,47.8 25.2,47.8 8.54,47.914 16,48.3 16.9,48.3 17.8,48.3 18.7,48.3 19.596,48.3 5.789,48.546 7.598,48.861 24,49 25.2,49 8.54,49.105 31.4,49.4 29.6,49.6 6.116,50.142 24,50.2 25.2,50.2 28.8,50.6 32,50.6 0.772,50.944 2.068,50.952 3.409,50.989 4.8,51.4 6.008,51.403 7.215,51.398 8.415,51.398 21.615,51.398 22.815,51.398 24.015,51.398 25.215,51.398 26.6,51.4 28,51.4 33,51.4 0.794,52.047 31.8,52.4 4.8,52.6 6.008,52.603 7.215,52.598 8.415,52.598 9.615,52.598 20.415,52.598 21.615,52.598 22.815,52.598 24.015,52.598 25.215,52.598 29.2,52.6 0.839,53.462 4.8,53.8 6.008,53.803 7.215,53.798 8.415,53.798 9.615,53.798 10.815,53.798 12.015,53.798 14.415,53.798 15.615,53.798 16.815,53.798 18.015,53.798 19.215,53.798 20.415,53.798 21.615,53.798 22.815,53.798 24.015,53.798 25.215,53.798 30.4,53.8 1.122,54.975 2.448,54.997 3.588,55.005 4.788,55.005 5.996,55.008 7.204,55.003 8.404,55.003 9.604,55.003 10.804,55.003 12.004,55.003 13.204,55.003 14.404,55.003 15.604,55.003 16.804,55.003 18.004,55.003 19.204,55.003 20.404,55.003 21.604,55.003 22.804,55.003 24.004,55.003 25.204,55.003
IMU_ENABLE: U1.30 U101.12 U102.5 U102.6 U102.12 U102.13 | length 35.2
  Top Layer w0.1: v1(12.855,46.004) 13.286,45.573 14.462,45.573 14.935,45.1 U1.30@14.985,45.1
  Top Layer w0.2: v1(28.764,38.96) v1@28.764,38.963
  Signal Layer 2 w0.1: v1(12.855,46.004) 12.446,45.595 12.446,43.38 13.282,42.544 13.282,38.956 13.015,38.688 13.015,37.605 v1(14.28,36.34)
  Signal Layer 3 w0.1: v1(14.28,36.34) 14.81,36.34 15.327,36.858 20.696,36.858 20.857,36.696 v1(22.007,36.696) 22.67,36.696 22.87,36.896 26.7,36.896 27.309,37.505 v1(28.764,38.96)
  Bottom Layer w0.1: v1(22.007,36.696) 22.054,36.649 22.404,36.649 22.454,36.599 ; 22.455,36.6 U102.6@23.095,36.6 ; U102.5@23.18,35.915 23.18,36.515 U102.6@23.095,36.6 ; U102.12@24.78,37.685 24.78,37.085 U102.13@24.865,37 23.78,37 23.38,36.6 U102.6@23.095,36.6
  Bottom Layer w0.2: U101.12@27.93,37.685 27.93,38.154 28.736,38.96 v1(28.764,38.96)
IMU_INT: R103.2 U1.17 U104.12 | length 31.8
  Top Layer w0.1: U1.17@17.885,49 17.919,49.034 17.919,49.619 v1(17.952,49.653) ; U104.12@19.23,23.625 19.23,23.34 19.82,22.75 R103.2@19.83,22.75 19.83,22.347 v1(19.822,22.339)
  Signal Layer 2 w0.1: v1(17.952,49.653) 18.768,48.837 18.888,48.837 19.153,48.572 19.153,43.051 19.797,42.406 19.797,41.874 19.215,41.291 19.215,40.545 19.005,40.336 19.005,38.384 19.215,38.175 19.215,35.936 18.738,35.46 18.738,33.495 19.343,32.89 19.343,31.919 18.845,31.421 18.845,23.316 v1(19.822,22.339)
IMU_SPI_CIPO: U102.3 U104.9 | length 23.6
  Top Layer w0.1: U104.9@17.73,23.675 17.73,22.949 v1(17.734,22.945)
  Signal Layer 2 w0.1: v1(22.287,20.03) 22.287,20.405 23.236,21.354 23.236,30.547 22.883,30.9 22.883,34.292 23.881,35.29 v1(23.936,35.29)
  Signal Layer 3 w0.1: v1(17.734,22.945) 18.871,21.808 20.76,21.808 22.23,20.339 22.23,20.087 v1(22.287,20.03)
  Bottom Layer w0.1: v1(23.936,35.29) 23.958,35.312 23.958,35.893 U102.3@23.98,35.915
IMU_SPI_COPI: U102.1 U104.24 | length 18.3
  Top Layer w0.1: U104.24@16.73,27.375 16.756,27.401 16.756,28.113 v1(16.782,28.139)
  Signal Layer 2 w0.1: v1(16.782,28.139) 16.782,28.959 16.622,29.118 16.622,30.056 16.998,30.432 16.998,35.026 16.798,35.226 v1(16.798,35.942)
  Signal Layer 3 w0.1: v1(16.798,35.942) 19.573,35.942 19.918,35.597 21.037,35.597 21.237,35.797 24.275,35.797 v1(24.922,35.15)
  Bottom Layer w0.1: U102.1@24.78,35.915 24.78,35.675 24.846,35.609 24.864,35.609 24.922,35.55 v1(24.922,35.15)
IMU_SPI_CS: R102.2 U101.11 U104.22 | length 20.8
  Top Layer w0.102: U104.22@17.73,27.325 17.73,27.66 17.945,27.875 18.905,27.875 R102.2@19.28,28.25 19.28,29.263 19.958,29.941 v1(19.958,29.99)
  Signal Layer 2 w0.1: v1(27.688,38.765) 27.691,38.762 27.691,35.841 27.385,35.535 27.385,34.273 v1(28.17,33.488)
  Signal Layer 3 w0.1: v1(19.958,29.99) 22.143,29.99 22.33,29.803 24.407,29.803 28.092,33.488 v1(28.17,33.488)
  Bottom Layer w0.102: U101.11@27.53,37.685 27.53,38.499 27.688,38.657 v1(27.688,38.765)
IMU_SPI_SCLK: U102.8 U104.23 | length 16.6
  Top Layer w0.102: U104.23@17.23,27.325 17.23,27.658 17.48,27.908 v1(17.48,27.977)
  Signal Layer 2 w0.1: v1(22.655,28.593) 22.655,35.222 22.772,35.34 v1(22.772,37.922)
  Signal Layer 3 w0.1: v1(17.48,27.977) 18.414,27.977 19.418,28.982 20.355,28.982 20.368,28.995 22.253,28.995 v1(22.655,28.593)
  Bottom Layer w0.102: v1(22.772,37.922) 23.131,37.922 23.131,37.954 23.18,37.905 U102.8@23.18,37.685
LED0: R29.2 U1.42 | length 15.5
  Top Layer w0.1: v1(18.272,30.824) 18.57,30.526 19.593,30.526 20.267,31.2 R29.2@20.277,31.2 ; v1(18.815,41.878) 18.838,41.902 18.838,42.328 19.385,42.875 U1.42@19.385,43.2
  Signal Layer 2 w0.1: v1(18.272,30.824) 18.272,30.871 18.23,30.913 18.23,35.658 18.815,36.243 18.815,37.973 18.596,38.191 18.596,40.581 18.815,40.799 v1(18.815,41.878)
LED1: R30.2 U1.43 | length 16.1
  Top Layer w0.1: R30.2@15.481,31.2 15.491,31.2 15.601,31.31 15.601,31.32 15.907,31.626 v1(15.907,32.342) ; v1(18.876,32.417) v1@18.905,32.417 ; v1(19.352,42.238) 19.885,42.771 U1.43@19.885,43.2
  Signal Layer 2 w0.1: v1(18.876,32.417) 18.876,33.02 18.465,33.431 18.465,35.562 19.015,36.112 19.015,38.082 18.796,38.3 18.796,40.44 19.015,40.659 19.015,41.384 19.352,41.721 v1(19.352,42.238)
  Signal Layer 3 w0.1: v1(15.907,32.342) 17.528,32.342 17.603,32.417 v1(18.876,32.417)
LESENSE_LC_EXCITE: R198.1 U1.11 | length 32
  Top Layer w0.1: v1(8.35,36.083) 8.915,36.083 9.344,36.512 R198.1@9.344,37.65 ; v1(20.635,50.664) 20.91,50.389 20.91,48.675 20.835,48.6 U1.11@20.785,48.6
  Signal Layer 2 w0.1: v1(8.35,36.083) 8.392,36.125 8.673,36.125 9.084,36.536 9.084,38.286 8.893,38.477 8.893,40.045 9.541,40.693 9.541,50.203 11.463,52.125 19.175,52.125 v1(20.635,50.664)
LESENSE_LC_SENSE: R196.1 U1.7 | length 24
  Top Layer w0.1: R196.1@7.836,38.064 7.846,38.064 8.016,38.234 8.016,38.347 v1(8.093,38.424) ; U1.7@20.785,46.6 21.639,46.6 v1(21.98,46.941)
  Signal Layer 2 w0.1: v1(20.009,39.985) 20.768,40.745 20.768,42.315 20.001,43.083 20.001,46.124 20.817,46.941 v1(21.98,46.941)
  Signal Layer 3 w0.1: v1(8.093,38.424) 10.675,38.424 10.989,38.111 12.459,38.111 13.444,39.095 14.015,39.095 15.255,40.335 16.27,40.335 16.62,39.985 v1(20.009,39.985)
MODULE_#RESET: C100.1 R209.2 R212.2 SW1.1 SW1.2 U1.1 | length 45.3
  Top Layer w0.1: SW1.2@15.505,35.13 SW1.1@19.655,35.13 SW1.1@19.712,35.073 ; v1(19.704,34.172) 19.74,34.208 19.74,34.856 19.796,34.912 19.873,34.912 SW1.1@19.712,35.073 ; v1(20.124,41.6) 21.008,42.484 21.008,43.377 20.91,43.475 20.91,43.525 20.835,43.6 U1.1@20.785,43.6 ; C100.1@21.083,35.073 SW1.1@19.712,35.073
  Signal Layer 2 w0.1: v1(20.124,41.6) 19.441,40.916 19.441,40.426 19.205,40.191 19.205,38.562 19.704,38.063 v1(19.704,34.172) 19.704,30.795 19.057,30.148 19.057,23.729 20.236,22.55 20.236,21.068 20.665,20.639 v1(20.665,18.848)
  Signal Layer 3 w0.1: v1(20.665,18.848) 20.739,18.774 22.79,18.774 23.359,18.204 26.713,18.204 27.51,19.002 28.528,19.002 v1(28.805,18.725)
  Bottom Layer w0.102: R209.2@26.53,19.4 27.38,18.55 27.43,18.55 27.98,19.1 28.43,19.1 v1(28.805,18.725)
MODULE_PA00: R135.2 U1.12 | length 60.8
  Top Layer w0.1: v1(16.098,17.931) 16.156,17.988 16.156,18.501 16.185,18.501 16.334,18.65 R135.2@16.555,18.65 ; v1(20.381,49.451) 20.383,49.449 20.383,49.052 U1.12@20.385,49.05
  Signal Layer 2 w0.1: v1(5.09,17.329) 5.12,17.358 5.12,30.537 8.095,33.513 8.095,35.194 9.314,36.413 9.314,38.339 9.093,38.56 9.093,39.959 9.741,40.607 9.741,50.111 11.534,51.905 18.689,51.905 20.381,50.213 v1(20.381,49.451)
  Signal Layer 3 w0.1: v1(5.09,17.329) 5.1,17.318 8.309,17.318 9.39,18.4 12.702,18.4 13.171,17.931 v1(16.098,17.931)
MODULE_PA07: U1.20 U900.C12 U900.C13 | length 39.8
  Top Layer w0.1: v1(15.935,50.711) 16.385,50.262 U1.20@16.385,49
  Signal Layer 2 w0.1: v1(10.045,20.95) 9.508,21.487 9.508,35.193 10.558,36.243 10.558,43.187 11.19,43.819 11.19,44.123 10.546,44.768 10.546,49.643 11.73,50.828 13.776,50.828 13.893,50.711 v1(15.935,50.711)
  Bottom Layer w0.1: U900.C12@9.83,23 U900.C13@9.83,22.5 9.83,21.961 10.045,21.746 v1(10.045,20.95)
MODULE_PA10: U1.23 U900.D11 U900.D12 | length 35.2
  Top Layer w0.1: v1(14.328,49.77) 14.985,49.113 U1.23@14.985,48.6
  Signal Layer 2 w0.1: v1(11.125,23.974) 11.112,23.96 10.05,23.96 9.708,24.302 9.708,35.105 10.758,36.155 10.758,43.104 11.413,43.759 11.413,44.184 10.746,44.851 10.746,49.544 11.83,50.628 13.693,50.628 13.972,50.349 13.972,50.126 v1(14.328,49.77)
  Bottom Layer w0.1: U900.D12@10.33,23 U900.D11@10.33,23.5 10.727,23.897 11.049,23.897 v1(11.125,23.974)
MODULE_PB01: R137.2 U1.10 | length 66.5
  Top Layer w0.1: v1(19.862,20.072) 19.862,19.62 19.861,19.619 R137.2@19.93,19.55 ; U1.10@20.785,48.1 21.087,48.1 21.625,48.638 v1(21.625,49.057)
  Signal Layer 2 w0.1: v1(4.637,19.445) 4.622,19.46 4.622,30.362 7.895,33.635 7.895,36.744 8.369,37.218 8.659,37.218 8.83,37.389 8.83,38.192 8.685,38.337 8.685,40.169 9.341,40.825 9.341,50.306 11.373,52.338 19.527,52.338 21.663,50.202 21.663,49.095 v1(21.625,49.057)
  Signal Layer 3 w0.1: v1(4.637,19.445) 4.916,19.724 6.346,19.724 7.035,19.035 11.76,19.035 12.53,19.804 17.689,19.804 17.761,19.732 19.52,19.732 19.861,20.072 v1(19.862,20.072)
MODULE_PC04: R136.2 U1.38 | length 28
  Top Layer w0.1: v1(17.304,42.602) 17.345,42.643 17.345,43.16 U1.38@17.385,43.2 ; R136.2@19.93,18.65 19.93,18.645 20.368,18.207 v1(20.368,18.114)
  Signal Layer 2 w0.1: v1(17.304,42.602) 17.304,42.105 17.088,41.889 17.088,40.782 17.747,40.122 17.747,38.625 17.198,38.076 17.198,30.312 16.849,29.962 16.849,29.447 18.64,27.655 18.64,21.513 19.462,20.691 19.462,19.01 20.358,18.114 v1(20.368,18.114)
MODULE_PC07: U1.41 U101.5 U101.6 U101.13 | length 19.2
  Top Layer w0.1: v1(18.342,41.424) 18.342,42.142 18.885,42.685 U1.41@18.885,43.2
  Signal Layer 2 w0.1: v1(18.258,36.452) 18.258,36.919 18.594,37.255 18.594,37.894 18.386,38.102 18.386,41.38 v1(18.342,41.424)
  Signal Layer 3 w0.1: v1(18.258,36.452) 19.166,36.452 19.361,36.647 20.556,36.647 21.006,36.197 22.636,36.197 23.135,36.696 25.74,36.696 25.968,36.469 v1(25.968,35.81)
  Bottom Layer w0.1: U101.6@26.245,36.6 26.295,36.65 26.543,36.65 26.898,37.005 28.01,37.005 U101.13@28.015,37 ; U101.6@26.28,36.6 26.33,36.55 U101.5@26.33,35.915
  Bottom Layer w0.25: v1(25.968,35.81) 26.016,35.858 26.305,35.858 26.33,35.883 U101.5@26.33,35.915
MODULE_PD00: U1.33 X2.1 | length 1.3
  Top Layer w0.2: X2.1@13.761,43.313 13.786,43.338 14.285,43.338 14.547,43.6 U1.33@14.985,43.6
MODULE_PD01: U1.32 X2.2 | length 1.6
  Top Layer w0.2: X2.2@13.65,44.75 13.972,44.75 14.296,44.425 14.296,44.349 14.545,44.1 U1.32@14.985,44.1
N16783896: R908.1 R909.2 U902.5 | length 1.3
  Bottom Layer w0.127: R909.2@9.015,42.52 U902.5@10.365,42.52
N16783941: R907.1 U902.7 | length 0.8
  Bottom Layer w0.127: U902.7@11.365,42.52 11.365,43.045 11.484,43.164 11.484,43.174 11.58,43.27 R907.1@11.59,43.27
N16783963: C918.1 U902.6 | length 0.8
  Bottom Layer w0.1: U902.6@10.865,42.52 10.865,43.195 C918.1@10.94,43.27
N16784657: C921.1 P901.1 P902.2 Q901.3 Q901.8 | length 93.4
  Signal Layer 2 w0.5: v1(6.091,11.192) 6.091,13.088 v1(9.816,16.813) ; v1(6.091,11.192) v1(6.091,10.409) 6.91,10.409 v1(6.921,10.42)
  Signal Layer 5 w0.5: v1(9.816,16.813) 9.816,17.276 9.38,17.712 9.38,21.435 9.6,21.655 9.6,23.229 9.062,23.767 9.062,32.267 v1(11.34,34.545)
  Signal Layer 5 w0.7: v1(21.38,24.871) 22.614,23.637 22.614,21.604 21.529,20.52 21.529,19.027 28.664,11.893 v1(28.664,11.279) 28.664,10.49 v1(28.7,10.454)
  Signal Layer 3 w0.7: v1(6.091,11.192) v1(6.091,10.409) 20.548,10.409 20.777,10.638 24.646,10.638 24.83,10.454 v1(28.7,10.454) 28.664,10.49 v1(28.664,11.279)
  Bottom Layer w0.3: v1(11.34,34.545) 11.69,34.895 11.69,35.712 Q901.8@11.873,35.895
  Bottom Layer w0.6: P901.1@6.086,9.273 v1@6.086,10.404 ; v1@6.091,10.408 v1(6.091,11.192) ; P901.1@6.858,8.502 P901.1@6.858,7.5 ; P901.1@6.858,7.5 6.921,7.563 v1(6.921,10.42) 6.91,10.409 v1(6.091,10.409) 6.091,8.267 P901.1@6.858,7.5
  Bottom Layer w0.7: P902.2@19.405,24.875 20.296,24.875 20.3,24.871 20.68,24.871 ; 20.68,24.875 21.376,24.875 v1(21.38,24.871) ; C921.1@27.98,16.6 27.98,12.179 v1@28.664,11.496 ; v1(28.664,11.279) 28.7,11.243 v1(28.7,10.454) 28.7,7.502 P901.1@28.702,7.5
N16942953: C106.1 U104.10 | length 0.9
  Top Layer w0.25: U104.10@18.23,23.525 18.23,23.377 18.55,23.057 18.55,22.785 C106.1@18.605,22.785
N16944331: R109.2 TP4.1 U105.3 | length 5.6
  Top Layer w0.1: U105.3@25.13,30.475 25.08,30.425 R109.2@25.08,29.7 25.347,29.7 25.711,29.336 27.549,29.336 27.812,29.599 v1(27.812,30.207)
  Bottom Layer w0.1: TP4.1@27.097,31.068 27.097,30.995 27.812,30.28 v1(27.812,30.207)
N16944525: R112.2 TP2.1 U107.5 | length 13.6
  Top Layer w0.1: v1(31.606,39.502) 31.625,39.484 32.041,39.484 R112.2@32.06,39.465
  Top Layer w0.2: R112.2@32.06,39.44 U107.5@32.06,38.59 U107.5@32.135,38.665
  Signal Layer 3 w0.1: v1(22.025,40.538) 22.551,40.013 24.578,40.013 24.823,40.257 30.851,40.257 v1(31.606,39.502)
  Bottom Layer w0.1: TP2.1@20.555,39.334 21.234,40.013 21.499,40.013 v1(22.025,40.538)
N17008241: C900.1 U900.J13 | length 1.4
  Bottom Layer w0.2: U900.J13@12.83,22.5 13.55,21.78 13.55,21.65 13.7,21.5 C900.1@13.75,21.5
N17008263: C903.1 C904.1 C905.1 L900.2 U900.M9 U900.M10 U900.N11 | length 5.4
  Bottom Layer w0.1: 14.605,24.7 14.655,24.75 15.299,24.75
  Bottom Layer w0.2: 14.605,24.7 14.53,24.7 U900.M9@14.33,24.5 U900.M10@14.33,24 U900.N11@14.83,23.5 15.355,22.975 15.83,22.975 C904.1@15.855,22.95 ; 15.299,24.75 15.354,24.75 15.374,24.77 15.72,24.77 15.78,24.83 C905.1@15.78,24.85
  Bottom Layer w0.3: C904.1@15.855,22.95 15.86,22.945 L900.2@16.43,22.945 17.01,22.945 C903.1@17.105,22.85 ; C903.1@17.15,22.87 C903.1@17.155,22.875
N17191783: LED900.2 R905.2 | length 1
  Top Layer w0.2: LED900.2@26.985,7.8 27.76,7.8 27.9,7.94 R905.2@27.9,7.95
N17218868: R141.1 SW100.3 SW100.4 | length 5.1
  Top Layer w0.1: SW100.4@24.91,3.275 SW100.3@29.06,3.275 29.075,3.29 R141.1@30.022,3.29
N17219122: R144.1 SW101.3 SW101.4 | length 5.4
  Top Layer w0.1: R144.1@5.372,1.048 6.433,1.048 6.584,1.199 10.586,1.199 SW101.4@10.66,1.125
N17219358: LED100.4 R135.1 | length 1.2
  Top Layer w0.2: R135.1@16.58,19.55 LED100.4@17.355,18.775 LED100.4@17.355,18.675
N17219362: LED100.3 R136.1 | length 0.8
  Top Layer w0.2: LED100.3@18.205,18.675 19.005,18.675 R136.1@19.03,18.65
N17219366: LED100.2 R137.1 | length 0.8
  Top Layer w0.2: LED100.2@18.205,19.525 19.005,19.525 R137.1@19.03,19.55
N17314136: Q200.5 R206.2 R207.1 | length 1.8
  Bottom Layer w0.125: Q200.5@25.53,21.1 26.53,21.1 R206.2@26.53,20.25
N17314162: Q200.6 R212.1 | length 2.6
  Bottom Layer w0.125: Q200.6@25.53,20.6 25.73,20.6 25.88,20.45 25.88,19.2 R212.1@26.53,18.55
N17314928: Q200.2 Q200.3 R208.2 | length 2.9
  Bottom Layer w0.102: R208.2@24.23,19.7 23.755,20.175 23.755,21.1 ; Q200.2@24.23,21.1 23.755,21.1 ; Q200.3@24.23,21.6 24.005,21.6 23.755,21.35 23.755,21.1
N17328899: Q200.4 R210.1 | length 1.1
  Bottom Layer w0.125: Q200.4@25.53,21.6 26.18,21.6 R210.1@26.53,21.95
N17359976: TP3.1 U106.7 | length 4
  Top Layer w0.1: v1(26.13,17.75) 26.237,17.75 U106.7@26.83,18.343
  Bottom Layer w0.1: TP3.1@23.38,17.8 24.38,17.8 24.68,17.5 25.88,17.5 v1(26.13,17.75) v1@26.205,17.675
N17377067: C198.1 L100.1 R197.1 | length 5
  Top Layer w0.1: L100.1@3.485,40.8 5.319,40.8 6.87,39.25 7.146,39.25 C198.1@7.171,39.275 7.791,39.275 R197.1@7.826,39.31
N17377071: C198.2 L100.2 R196.2 | length 5
  Top Layer w0.1: L100.2@3.485,36.8 5.321,36.8 6.585,38.064 R196.2@7.236,38.064 7.204,38.097 7.204,38.692 C198.2@7.171,38.725
N17377075: C199.1 R197.2 R198.2 | length 1.5
  Top Layer w0.1: R197.2@8.726,39.31 8.625,39.209 C199.1@8.625,38.62 9.274,38.62 R198.2@9.344,38.55
N17377459: R6.2 SW1.3 SW1.4 | length 5.7
  Top Layer w0.1: R6.2@14.527,38.328 14.537,38.328 14.647,38.218 14.647,38.208 15.095,37.76 15.095,37.554 15.369,37.28 SW1.4@15.505,37.28 SW1.3@19.655,37.28
N17389062: Q902.2 R916.2 R917.1 R934.2 | length 2.1
  Bottom Layer w0.305: R934.2@9.489,33.977 9.489,33.987 9.497,33.995 9.497,34.538 9.687,34.729 9.687,35.293 Q902.2@9.69,35.295 ; R934.2@9.497,33.995 R916.2@10.165,33.995
N17389066: R934.1 TP900.1 | length 1.1
  Bottom Layer w0.2: R934.1@9.489,33.377 9.505,33.362 9.505,32.265 TP900.1@9.52,32.25
N17389104: Q902.5 Q902.6 R918.1 | length 1.9
  Bottom Layer w0.152: Q902.5@9.69,36.595 9.69,37.345 9.696,37.351 9.696,37.361 9.78,37.445 R918.1@9.79,37.445 9.8,37.445 9.884,37.361 9.884,37.351 10.19,37.045 Q902.6@10.19,36.595
N17431907: LED0.1 R29.1 | length 0.9
  Top Layer w0.3: R29.1@20.877,31.2 20.881,31.204 20.881,32.046 LED0.1@20.885,32.05
N17431911: LED1.1 R30.1 | length 0.9
  Top Layer w0.3: R30.1@14.881,31.2 14.883,31.202 14.883,32.048 LED1.1@14.885,32.05
SENSOR_I2C_SCL: R107.2 U101.3 U105.5 U106.2 U107.3 U108.6 | length 68.1
  Top Layer w0.1: U108.6@3.64,45.3 3.67,45.3 3.815,45.155 3.815,45.016 3.895,44.936 v1@3.895,44.828 ; U105.5@24.48,32.125 R107.2@24.48,32.95 24.489,32.95 24.599,33.06 24.599,33.26 24.803,33.464 v1(24.803,33.573) ; R107.2@24.49,32.95 27.038,32.95 27.903,33.815 v1(27.903,34.946) ; v1(24.88,21.1) 25.48,20.5 25.688,20.5 U106.2@26.33,19.858 ; v1(33.96,35.48) U107.3@33.96,36.19
  Signal Layer 2 w0.1: v1(24.803,33.573) 24.803,32.392 25.23,31.965 25.23,29.941 25.201,29.911 24.538,29.249 24.538,27.875 24.079,27.416 24.079,26.425 25.06,25.444 25.06,24.947 24.802,24.688 24.802,23.835 25.249,23.388 25.249,21.469 v1(24.88,21.1) ; v1(27.903,34.946) 27.891,34.958 27.891,37.775 28.208,38.092 28.208,38.927 28.055,39.079 v1(28.055,39.824)
  Signal Layer 3 w0.1: v1@3.895,44.828 3.895,46.423 4.228,46.756 5.862,46.756 6.777,45.841 6.777,42.854 8.017,41.614 9.183,41.614 10.513,40.284 13.315,40.284 14.145,41.114 16.489,41.114 16.888,40.715 20.363,40.715 21.736,39.341 26.939,39.341 27.405,39.807 28.038,39.807 v1(28.055,39.824) ; v1(27.903,34.946) 33.426,34.946 v1(33.96,35.48)
  Bottom Layer w0.1: U101.3@27.13,35.915 27.16,35.885 27.16,35.505 27.413,35.252 27.596,35.252 v1(27.903,34.946)
  other v1: 3.93,44.76
SENSOR_I2C_SDA: R108.2 U101.8 U105.2 U106.4 U107.1 U108.1 | length 67.5
  Top Layer w0.1: v1@3.614,49.08 3.614,48.226 U108.1@3.64,48.2 ; v1(24.18,18.95) 24.255,19.025 25.747,19.025 U106.4@25.823,19.1 ; R108.2@24.48,29.7 U105.2@24.48,30.475 24.649,30.644 24.624,30.67 24.624,31.348 v1(24.63,31.354) ; v1(32.036,35.439) 32.036,36.166 U107.1@32.06,36.19
  Signal Layer 2 w0.1: v1(24.18,18.95) 23.48,19.65 23.48,30.204 v1(24.63,31.354) 23.733,32.251 23.733,33.803 24.095,34.165 25.008,34.165 25.854,35.01 v1(25.882,35.01) ; v1@25.885,35.041 26.454,35.611 26.454,36.236 25.899,36.791 25.899,38.013 25.591,38.322 25.591,39.549 v1(25.899,39.857)
  Signal Layer 3 w0.1: v1@3.614,49.08 3.614,47.514 4.159,46.969 5.972,46.969 6.977,45.965 6.977,42.969 8.088,41.858 9.274,41.858 10.644,40.488 13.221,40.488 14.048,41.314 16.582,41.314 16.971,40.925 20.514,40.925 21.626,39.813 25.855,39.813 v1(25.899,39.857) ; v1(25.882,35.01) 27.089,35.01 27.517,35.439 v1(32.036,35.439)
  Bottom Layer w0.1: v1(25.899,39.857) 25.899,38.356 26.33,37.925 U101.8@26.33,37.685
  other v1: 3.63,49.065
USB_PGOOD: R929.1 U900.E1 | length 7.9
  Signal Layer 2 w0.1: v1(10.779,34.965) 10.773,34.959 10.773,33.051 11.121,32.703 v1(11.121,30.808)
  Bottom Layer w0.1: v1(10.779,34.965) 10.807,34.993 10.807,35.787 R929.1@10.915,35.895 ; U900.E1@10.83,28.5 10.58,28.75 10.58,30.268 v1(11.121,30.808)
USBC_CC1: D900.6 P900.A5 R621.2 | length 2.3
  Top Layer w0.203: R621.2@16.3,8.7 16.3,8.204 16.487,8.018 16.487,7.408 P900.A5@16.535,7.36 ; R621.2@16.3,8.781 16.358,8.722 16.465,8.722 16.487,8.7 D900.6@17.165,8.7
USBC_CC2: D900.1 P900.B5 R620.2 | length 2.3
  Top Layer w0.3: D900.1@18.865,8.7 19.58,8.7 19.669,8.789 19.679,8.789 19.685,8.782 19.685,8.282 19.535,8.132 P900.B5@19.535,7.36
USBC_VBUS: D900.5 L901.1 P900.A4_B9 P900.B4_A9 | length 50.7
  Top Layer w0.3: P900.A4_B9@15.385,7.36 15.235,7.51 15.235,8.111 15.002,8.344 15.002,9.024 15.178,9.2 D900.5@17.165,9.2
  Top Layer w0.5: v1(6.608,4.203) v1@6.625,4.186 ; P900.A4_B9@15.385,7.36 15.435,7.31 15.435,6.669 16.58,5.524 18.958,5.524 20.135,6.7 20.135,7.31 P900.B4_A9@20.185,7.36
  Top Layer w0.7: v1@6.625,4.186 15.242,4.186 16.58,5.524
  Signal Layer 5 w0.7: v1(6.608,4.203) 6.597,4.192 5.153,4.192 4.59,4.755 4.59,13.067 6.493,14.969 14.126,14.969 16.062,16.905 16.798,17.641 16.798,20.536 v1(16.695,20.64) 16.499,20.836 v1(16.499,21.25)
  Bottom Layer w0.5: v1(16.695,20.64) 16.695,20.105 L901.1@16.8,20
VDD_IMU: C104.1 C105.1 C115.1 R102.1 R103.1 R932.2 U102.11 U104.8 U104.13 | length 47.5
  Top Layer w0.2: U104.13@19.855,24.25 C105.1@20.755,24.25
  Top Layer w0.25: U104.8@17.23,23.675 17.23,23.368 16.967,23.104 16.967,22.762 C115.1@16.955,22.75 16.955,21.926 v1(17.519,21.362) ; C105.1@20.675,24.25 20.681,24.25 20.716,24.215 20.716,23.684 20.718,23.682 20.683,23.647 20.683,23.627 20.435,23.378 20.435,22.785 20.43,22.78 R103.1@20.43,22.75 20.462,22.718 20.789,22.718 20.8,22.707 v1(20.836,22.707)
  Top Layer w0.3: R102.1@19.88,28.25 19.89,28.26 19.9,28.26 20.197,28.557 20.496,28.557 v1(20.534,28.595)
  Signal Layer 5 w0.4: v1(17.519,21.362) 17.523,21.358 19.618,21.358 20.372,22.111 20.372,22.215 20.836,22.68 v1(20.836,22.707) 19.594,23.949 19.594,27.932 20.238,28.576 20.515,28.576 v1(20.534,28.595) 20.534,28.622 20.968,29.057 20.968,31.074 22.671,32.777 22.671,35.743 24.696,37.768 24.696,38.359 v1(24.715,38.378)
  Signal Layer 3 w0.35: v1(5.958,25.015) 6.751,25.807 8.525,25.807 11.132,23.2 14.516,23.2 15.006,23.69 19.853,23.69 v1(20.836,22.707)
  Bottom Layer w0.2: U102.11@24.38,37.685 24.38,37.996 24.715,38.331 v1(24.715,38.378)
  Bottom Layer w0.25: v1(5.958,25.015) 5.966,25.015 6.102,25.15 R932.2@6.808,25.15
